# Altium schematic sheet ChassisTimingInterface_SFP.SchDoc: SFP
size B; Author: M. Pirello; Organization: LIGO Laboratory; Address1: California Institute of Technology; Address2: Massachusetts Institute of Technology; Address3: National Science Foundation; Address4: Australia 2086; DocumentNumber: 3; SheetNumber: 9; SheetTotal: 12; Size: B
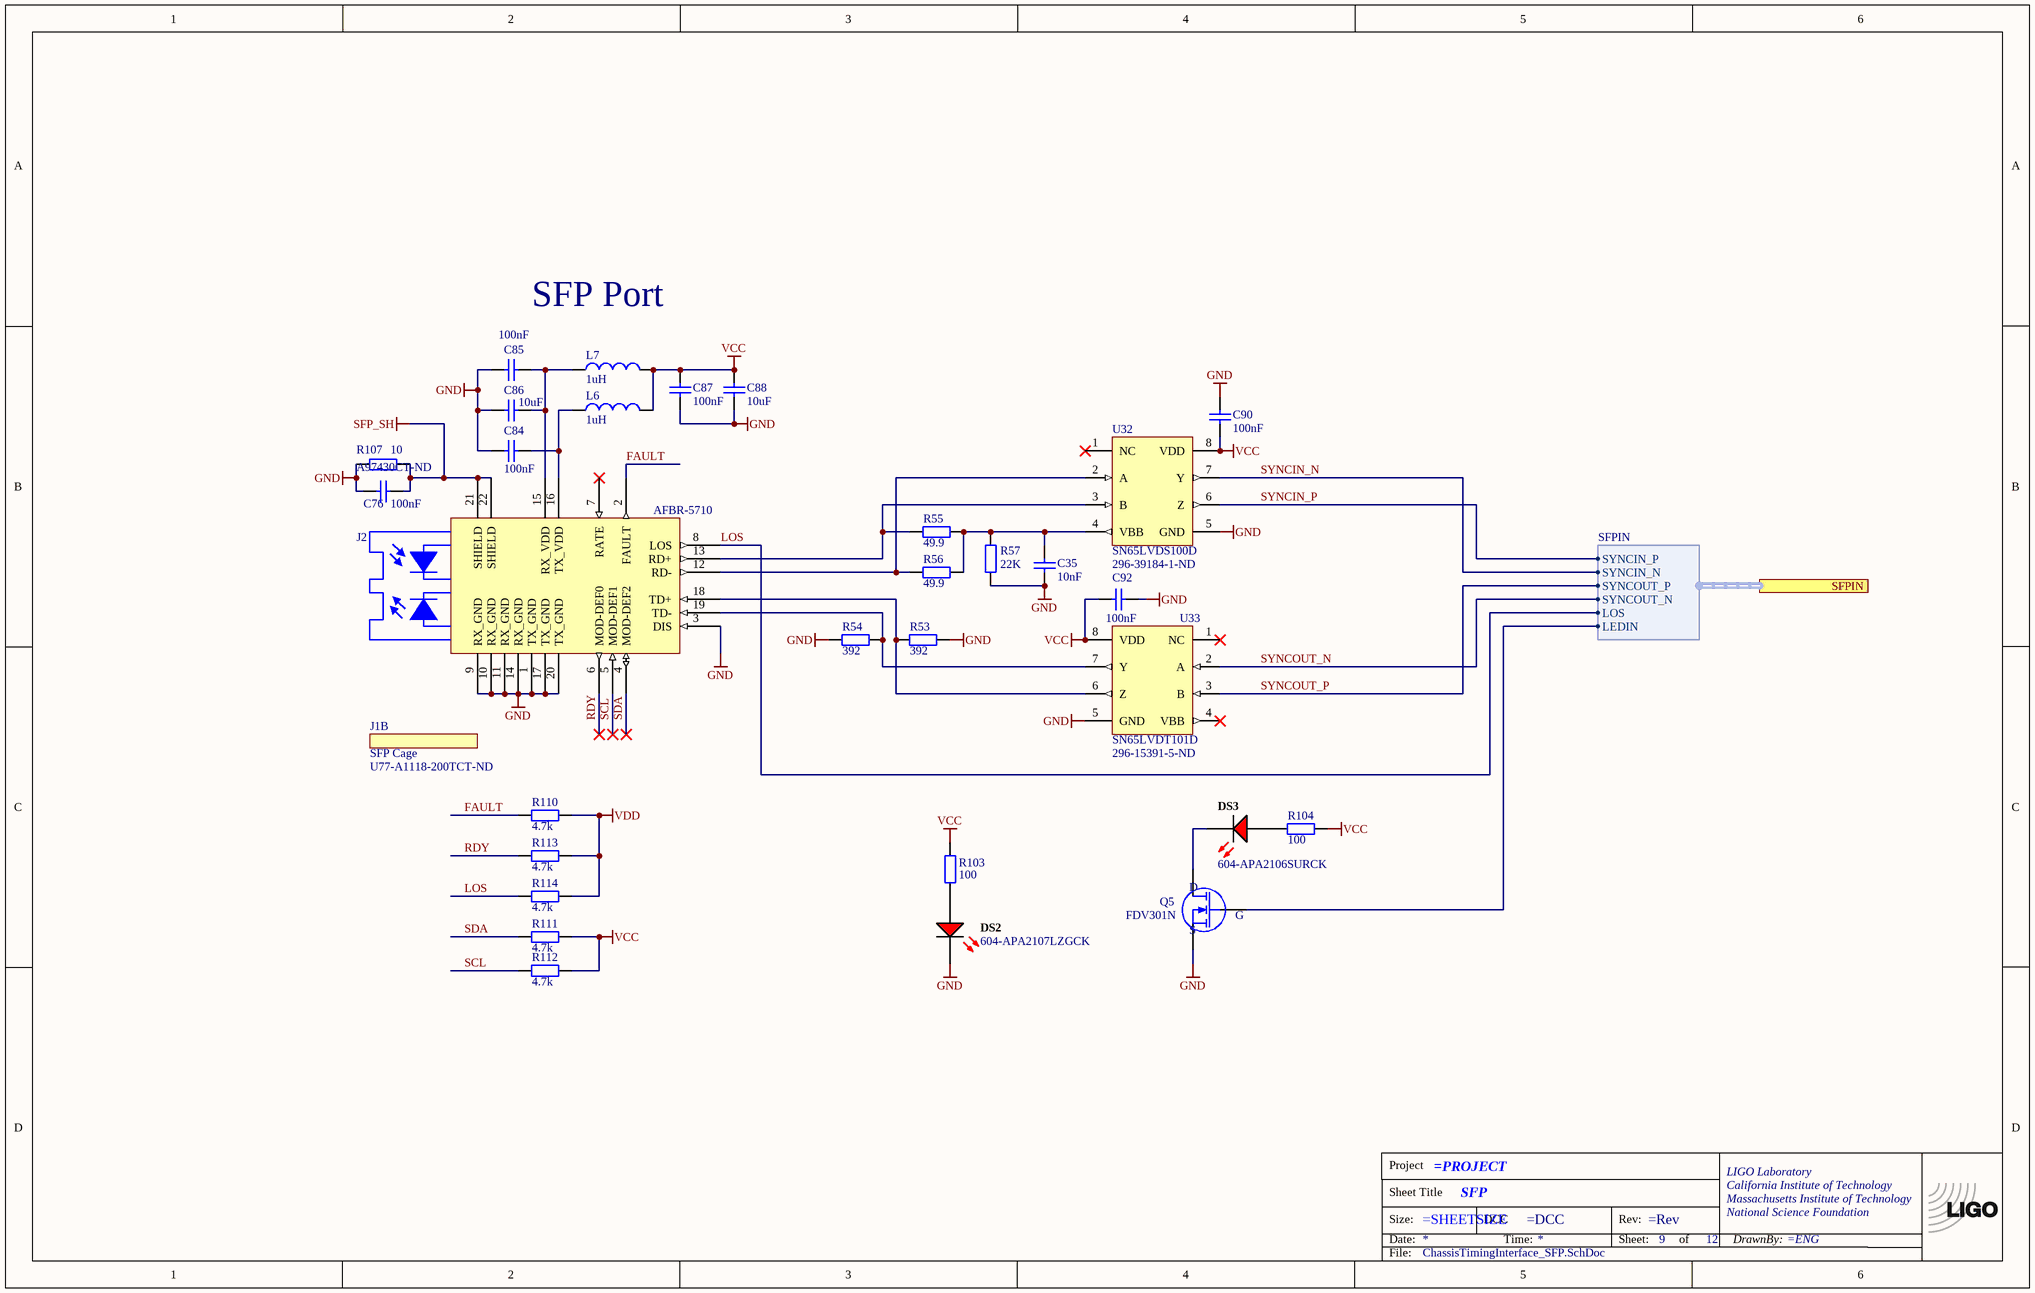
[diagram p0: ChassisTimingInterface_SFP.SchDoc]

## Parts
*  TitleBlock  (value not drawn)  (graphical)
C35  10nF  [CC1005-0402]
C76  100nF  [CC1005-0402]
C84  100nF  [CC1005-0402]
C85  100nF  [CC1005-0402]
C86  10uF  [CC2013-0805]
C87  100nF  [CC1005-0402]
C88  10uF  [CC2013-0805]
C90  100nF  [CC1005-0402]
C92  100nF  [CC1005-0402]
DS2  604-APA2107LZGCK  [KING-LED2107-13-RED-2_V]
DS3  604-APA2106SURCK  [KING-LED2107-13-RED-2_V]
J1B  SFP Cage  Supplier Part Number 1: U77-A1118-200TCT-ND  (mechanical)
J2  AFBR-5710  Supplier Part Number 1: A97430CT-ND  [MSA/SFP2x10]
L6  1uH  [CL2520-1008]
L7  1uH  [CL2520-1008]
Q5  FDV301N  [SO-G3/C2.25]
R53  392  [CR2012-0805]
R54  392  [CR2012-0805]
R55  49.9  [CR1608-0603]
R56  49.9  [CR1608-0603]
R57  22K  [CR2012-0805]
R103  100  [CR1608-0603]
R104  100  [CR1608-0603]
R107  value 10  [CR1005-0402]  (hidden comment: 10.0)
R110  4.7k  [CR1005-0402]
R111  4.7k  [CR1005-0402]
R112  4.7k  [CR1005-0402]
R113  4.7k  [CR1005-0402]
R114  4.7k  [CR1005-0402]
U32  SN65LVDS100D  Supplier Part Number 1: 296-39184-1-ND  [MSOP8]
U33  SN65LVDT101D  Supplier Part Number 1: 296-15391-5-ND  [MSOP8]

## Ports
SFPIN (harness SFPIN)

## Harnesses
SFPIN: SYNCIN_N, SYNCIN_P, SYNCOUT_N, SYNCOUT_P, LEDIN, LOS

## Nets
GND: C35.1 C76.2 C84.1 C85.1 C86.1 C87.1 C88.1 C90.1 C92.1 DS2.1(K) J2.1(TX_GND) J2.3(DIS) J2.9(RX_GND) J2.10(RX_GND) J2.11(RX_GND) J2.14(RX_GND) J2.17(TX_GND) J2.20(TX_GND) Q5.2(S) R53.2 R54.1 R57.2 R107.2 U32.5(GND) U33.5(GND)
SFP_SH: C76.1 J2.21(SHIELD) J2.22(SHIELD) R107.1
VCC: C87.2 C88.2 C90.2 C92.2 L6.2 L7.2 R103.2 R104.2 R111.2 R112.2 U32.8(VDD) U33.8(VDD)
VDD: R110.2 R113.2 R114.2
FAULT: J2.2(FAULT) R110.1
LOS: J2.8(LOS) R114.1 ; port SFPIN.LOS
RDY: J2.6(MOD-DEF0) R113.1
SCL: J2.5(MOD-DEF1) R112.1
SDA: J2.4(MOD-DEF2) R111.1
SYNCIN_N: U32.7(Y) ; port SFPIN.SYNCIN_N
SYNCIN_P: U32.6(Z) ; port SFPIN.SYNCIN_P
SYNCOUT_N: U33.2(A) ; port SFPIN.SYNCOUT_N
SYNCOUT_P: U33.3(B) ; port SFPIN.SYNCOUT_P
NetC35_2: C35.2 R55.1 R56.1 R57.1 U32.4(VBB)
NetC84_2: C84.2 J2.16(TX_VDD) L6.1
NetC85_2: C85.2 C86.2 J2.15(RX_VDD) L7.1
NetDS2_2: DS2.2(A) R103.1
NetDS3_1: DS3.1(K) Q5.3(D)
NetDS3_2: DS3.2(A) R104.1
NetJ2_12: J2.12(RD-) R56.2 U32.2(A)
NetJ2_13: J2.13(RD+) R55.2 U32.3(B)
NetJ2_18: J2.18(TD+) R53.1 U33.6(Z)
NetJ2_19: J2.19(TD-) R54.2 U33.7(Y)
NetQ5_1: Q5.1(G) ; port SFPIN.LEDIN

Not connected (* = marked no-connect by the designer): J2 7(RATE)* 23(POST) 24(POST); U32 1(NC)*; U33 1(NC)* 4(VBB)*

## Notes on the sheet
- SFP Port

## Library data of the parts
C35 = ChipCap: C0402 0.01uF; Part Number: 311-1349-1-ND; Tolerance: 10%
C76 C84 C85 C87 C90 C92 = ChipCap: C0402 0.1uF; Part Number: 1276-6720-1-ND; Tolerance: 10%
C86 C88 = ChipCap: C0805 10uF; Part Number: 1276-6454-1-ND; Tolerance: 10%
DS2 = CMP-0245-00001-1: 2.1x0.7mm Right Angle SMT LED, 1.3mm Thickness, Green
DS3 = CMP-0245-00001-1: 2.1x0.7mm Right Angle SMT LED, 1.3mm Thickness, Red
J1B = Partlist
J2 = AFBR-5710: fiber optic transceiver, 1.25GB/s, MM, LC, SFP
L6 L7 = ChipInductor: Inductor; Part Number: 994-1008LS-102XJLB
Q5 = FDV301N: FDV301N, Digital FET, N-channel, SOT23; Part Number: FDV301NCT-ND
R53 R54 = ChipRes1: R0805 392; Part Number: P20236CT-ND; Tolerance: 0.1%
R55 R56 = ChipRes1: R0603 49.9; Part Number: RR08Q49.9DCT-ND; Tolerance: 0.1%
R57 = ChipRes1: R0805 22k; Part Number: RR12P22.0KDCT-ND; Tolerance: 0.1%
R103 R104 = ChipRes1: R0603 100; Part Number: RR08P100DCT-ND; Tolerance: 0.1%
R107 = ChipRes1: R0402 10; Part Number: A127127CT-ND; Tolerance: 0.1%
R110-R114 = ChipRes1: R0402 4.7k; Part Number: RR05P4.7KDCT-ND; Tolerance: 0.1%
U32 U33 = SN65LVDS100: DIFF TRANSLATOR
